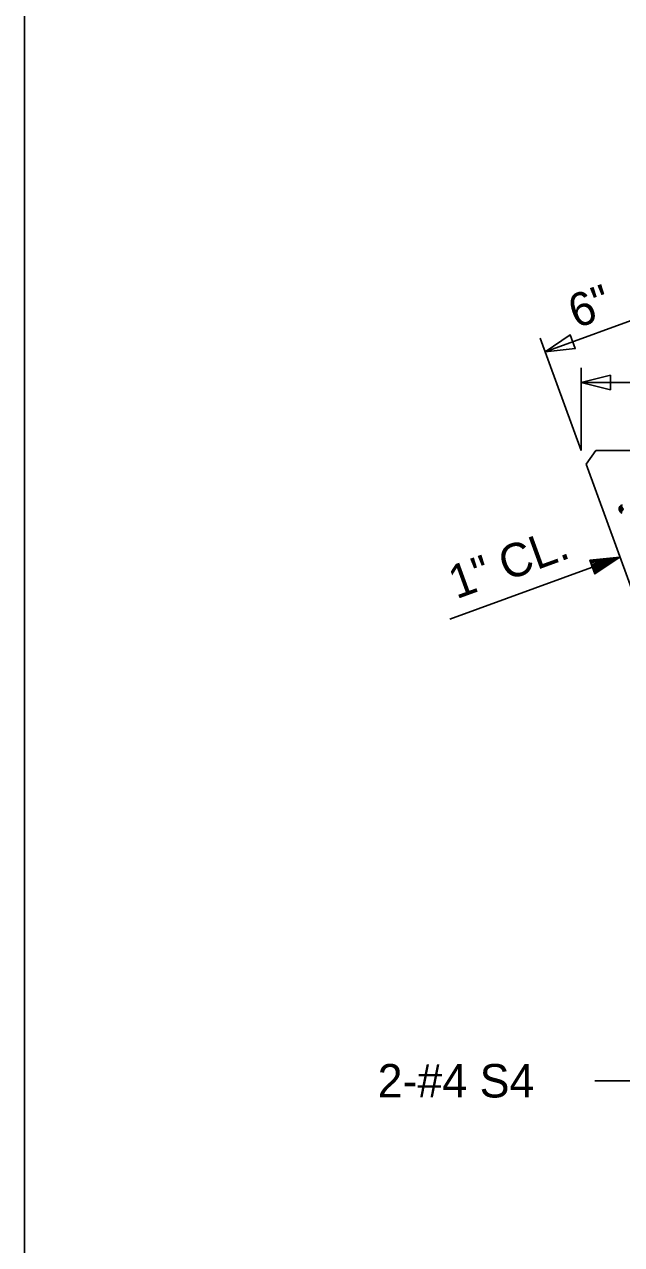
# Model space of a CAD drawing. Extents: x 0 to 177, y -1 to 130.
# Drawn here: x 124.81 to 127.36, y 89.92 to 95.14 of the extents above; entities that cross this region are included whole.
import ezdxf

# ---------------------------------------------------------------- set-up
doc = ezdxf.new("R2010")
doc.units = 0
for name, color, linetype in [('Arrowhead Terminators CELL', 7, 'Continuous'), ('Dimension Lines', 7, 'Continuous'), ('Plan Sheet', 7, 'Continuous'), ('Rebar Lines', 7, 'Continuous'), ('Sup Concrete Girder Lines', 7, 'Continuous'), ('Text', 7, 'Continuous')]:
    doc.layers.add(name, color=color, linetype=linetype)

msp = doc.modelspace()

# ---------------------------------------------------------------- linework, layer by layer
at = {"layer": 'Arrowhead Terminators CELL'}
for points in [[(127.0359, 93.7366), (127.1641, 93.75), (127.1427, 93.8087)], [(127.1894, 93.6051), (127.3144, 93.5739), (127.3144, 93.6364)]]:
    msp.add_lwpolyline(points, close=True, dxfattribs=at)
at = {"layer": 'Dimension Lines'}
for p, q in [((127.5058, 93.9076), (127.0359, 93.7366)), ((127.1894, 93.3146), (127.0146, 93.7953)), ((127.1894, 93.3146), (127.1894, 93.6676)), ((130.9813, 93.6051), (127.1894, 93.6051)), ((126.6282, 92.5945), (127.3553, 92.8591))]:
    msp.add_line(p, q, dxfattribs=at)
for points in [[(127.2377, 92.8164), (127.2356, 92.8222), (127.3553, 92.8591), (127.2334, 92.8281), (127.2312, 92.834), (127.3553, 92.8591), (127.2292, 92.8399), (127.2271, 92.8458), (127.3553, 92.8591), (127.2484, 92.787), (127.2463, 92.7929), (127.3553, 92.8591), (127.2442, 92.7988), (127.2421, 92.8046), (127.3553, 92.8591), (127.2398, 92.8105), (127.2271, 92.8458), (127.2484, 92.787), (127.3553, 92.8591), (127.2271, 92.8458)], [(127.2472, 90.6214), (127.5032, 90.6214), (128.1893, 91.0712)]]:
    msp.add_lwpolyline(points, dxfattribs=at)
at = {"layer": 'Plan Sheet'}
msp.add_line((124.8097, 119.1354), (124.8097, -0.8646), dxfattribs=at)
at = {"layer": 'Rebar Lines'}
for points in [[(127.3517, 93.0616), (127.3518, 93.0684), (127.3546, 93.0747), (127.3596, 93.0795), (127.366, 93.082)], [(127.366, 93.082), (127.3596, 93.0795), (127.3691, 93.0646), (127.3546, 93.0747), (127.3518, 93.0684), (127.3691, 93.0646), (127.3542, 93.0552), (127.359, 93.0502), (127.3691, 93.0646)], [(127.3652, 93.0475), (127.359, 93.0502), (127.3542, 93.0552), (127.3517, 93.0616), (127.3691, 93.0646)]]:
    msp.add_lwpolyline(points, dxfattribs=at)
at = {"layer": 'Sup Concrete Girder Lines'}
for p, q in [((127.2519, 93.3146), (127.2108, 93.2559)), ((127.2519, 93.3146), (132.0247, 93.3146)), ((128.2813, 90.3146), (127.2108, 93.2559))]:
    msp.add_line(p, q, dxfattribs=at)

# ---------------------------------------------------------------- texts
at = {"layer": 'Text'}
for s, rotation, p in [('6"', 19.9877, (127.1677, 93.8347)), ('1" CL.', 20.0021, (126.6559, 92.6784))]:
    msp.add_text(s, height=0.14302, rotation=rotation, dxfattribs=at).set_placement(p)
msp.add_text('2-#4 S4', height=0.14302, dxfattribs=at).set_placement((126.3195, 90.5499))

doc.saveas('drawing.dxf')
